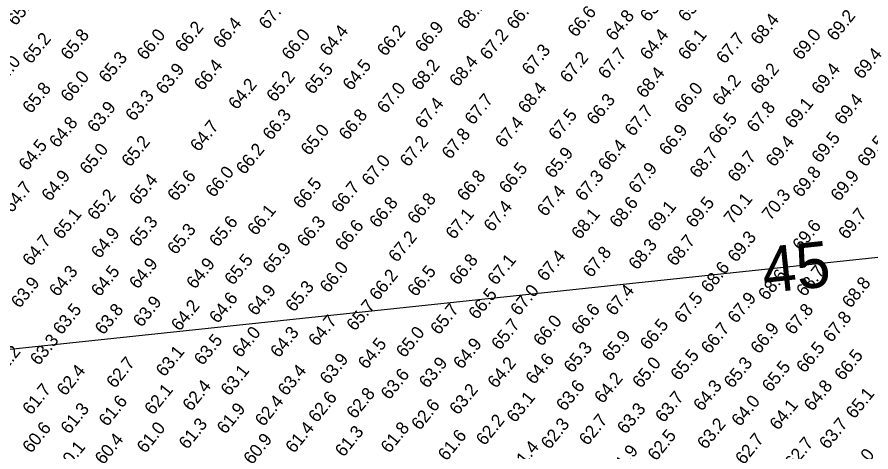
# Model space of a CAD drawing. Extents: x 401290 to 405690, y 1190598 to 1193998.
# Drawn here: x 402509 to 403181, y 1192273 to 1192614 of the extents above; entities that cross this region are included whole.
import ezdxf

# ---------------------------------------------------------------- set-up
doc = ezdxf.new("R2010")
doc.units = 0
for name, color, linetype in [('C-CHAN-CNTR', 7, 'Continuous'), ('V-CHAN-TEXT', 7, 'Continuous'), ('V-TOPO-SOUN', 7, 'Continuous')]:
    doc.layers.add(name, color=color, linetype=linetype)

msp = doc.modelspace()

# ---------------------------------------------------------------- linework, layer by layer
at = {"layer": 'C-CHAN-CNTR'}
msp.add_line((401937.03, 1192293.37), (404340.86, 1192548.17), dxfattribs=at)

# ---------------------------------------------------------------- texts
at = {"layer": 'V-CHAN-TEXT'}
msp.add_text('45', height=36, rotation=6.05064, dxfattribs=at).set_placement((403097.37, 1192397.42))
at = {"layer": 'V-TOPO-SOUN'}
for s, p in [('65.1 ', (402508.18, 1192607.01)), ('67.0 ', (402706.18, 1192604.02)), ('66.8 ', (402901.19, 1192604.02)), ('63.1 ', (403006.18, 1192610.02)), ('65.4 ', (403036.2, 1192610.02)), ('68.1 ', (402862.18, 1192604.02)), ('66.6 ', (402949.19, 1192598.02)), ('64.8 ', (402979.18, 1192595.03)), ('68.4 ', (403093.19, 1192592.01)), ('69.2 ', (403153.19, 1192595.03)), ('66.2 ', (402640.2, 1192586.01)), ('66.4 ', (402670.19, 1192589.03)), ('66.9 ', (402829.18, 1192586.01)), ('65.2 ', (402520.19, 1192577.02)), ('65.8 ', (402550.18, 1192580)), ('66.0 ', (402610.18, 1192580)), ('66.0 ', (402724.19, 1192580)), ('64.4 ', (402754.18, 1192583.02)), ('66.2 ', (402799.19, 1192583.02)), ('67.2 ', (402880.19, 1192580)), ('64.4 ', (403006.18, 1192580)), ('66.1 ', (403036.2, 1192580)), ('67.7 ', (403066.19, 1192577.02)), ('69.0 ', (403126.19, 1192580)), ('67.3 ', (402913.2, 1192568.03)), ('67.7 ', (402973.17, 1192565.01)), ('69.4 ', (403174.19, 1192565.01)), ('64.0 ', (402496.17, 1192559.01)), ('65.3 ', (402580.2, 1192562.03)), ('64.5 ', (402772.19, 1192556.02)), ('68.4 ', (402856.18, 1192559.01)), ('67.2 ', (402943.19, 1192562.03)), ('63.9 ', (402625.18, 1192553.04)), ('66.4 ', (402655.2, 1192556.02)), ('65.5 ', (402742.17, 1192553.04)), ('68.2 ', (402826.19, 1192556.02)), ('68.4 ', (403003.19, 1192550.02)), ('68.2 ', (403093.19, 1192553.04)), ('69.4 ', (403141.19, 1192553.04)), ('66.0 ', (402550.18, 1192547.03)), ('65.2 ', (402712.18, 1192547.03)), ('64.2 ', (403063.2, 1192544.01)), ('65.8 ', (402520.19, 1192538.01)), ('64.2 ', (402682.2, 1192541.03)), ('67.0 ', (402799.19, 1192538.01)), ('68.4 ', (402910.18, 1192538.01)), ('66.0 ', (403033.18, 1192538.01)), ('63.3 ', (402601.19, 1192532.01)), ('67.7 ', (402868.19, 1192529.02)), ('67.4 ', (402829.18, 1192526.04)), ('66.3 ', (402964.18, 1192529.02)), ('67.8 ', (403090.2, 1192523.02)), ('69.1 ', (403120.19, 1192526.04)), ('69.4 ', (403159.2, 1192529.02)), ('63.9 ', (402571.17, 1192523.02)), ('66.3 ', (402709.2, 1192517.01)), ('66.8 ', (402769.17, 1192517.01)), ('67.5 ', (402934.2, 1192517.01)), ('67.7 ', (402994.17, 1192520.03)), ('64.8 ', (402541.19, 1192511.01)), ('67.4 ', (402892.2, 1192511.01)), ('66.5 ', (403060.18, 1192514.03)), ('64.7 ', (402652.18, 1192508.02)), ('65.0 ', (402739.18, 1192505.01)), ('66.9 ', (403021.17, 1192505.01)), ('65.2 ', (402598.17, 1192496.02)), ('67.2 ', (402817.2, 1192496.02)), ('67.8 ', (402850.18, 1192502.02)), ('69.4 ', (403105.19, 1192496.02)), ('69.5 ', (403141.19, 1192499.03)), ('69.5 ', (403177.18, 1192496.02)), ('64.5 ', (402517.17, 1192493.03)), ('65.0 ', (402565.2, 1192490.01)), ('66.2 ', (402688.2, 1192490.01)), ('66.4 ', (402973.17, 1192493.03)), ('65.9 ', (402931.18, 1192487.03)), ('68.7 ', (403045.19, 1192487.03)), ('69.7 ', (403075.17, 1192484.01)), ('67.0 ', (402787.18, 1192481.02)), ('65.6 ', (402634.2, 1192469.01)), ('66.0 ', (402664.18, 1192472.03)), ('66.5 ', (402895.19, 1192475.02)), ('67.9 ', (402997.19, 1192475.02)), ('69.8 ', (403126.19, 1192472.03)), ('64.9 ', (402535.18, 1192469.01)), ('65.4 ', (402604.18, 1192466.03)), ('66.5 ', (402733.18, 1192463.01)), ('66.8 ', (402862.18, 1192469.01)), ('67.3 ', (402955.19, 1192469.01)), ('69.9 ', (403156.18, 1192469.01)), ('64.7 ', (402505.2, 1192460.02)), ('66.7 ', (402763.2, 1192460.02)), ('67.4 ', (402925.18, 1192457.01)), ('65.2 ', (402571.17, 1192454.02)), ('66.8 ', (402823.17, 1192451.04)), ('70.1 ', (403072.19, 1192451.04)), ('70.3 ', (403102.18, 1192454.02)), ('66.8 ', (402793.19, 1192448.02)), ('67.4 ', (402883.18, 1192445.03)), ('68.6 ', (402982.2, 1192448.02)), ('69.1 ', (403012.18, 1192445.03)), ('69.5 ', (403042.2, 1192448.02)), ('65.1 ', (402544.17, 1192439.03)), ('66.1 ', (402697.19, 1192442.01)), ('67.1 ', (402853.19, 1192439.03)), ('68.1 ', (402952.18, 1192439.03)), ('69.7 ', (403162.18, 1192439.03)), ('65.3 ', (402604.18, 1192433.02)), ('65.6 ', (402667.17, 1192433.02)), ('66.3 ', (402736.2, 1192433.02)), ('66.6 ', (402766.19, 1192430.01)), ('69.6 ', (403126.19, 1192430.01)), ('64.9 ', (402574.19, 1192424.03)), ('65.3 ', (402634.2, 1192427.02)), ('64.7 ', (402520.19, 1192418.03)), ('67.2 ', (402808.18, 1192421.02)), ('68.7 ', (403027.18, 1192418.03)), ('69.3 ', (403075.17, 1192421.02)), ('65.9 ', (402709.2, 1192412.03)), ('67.8 ', (402961.2, 1192409.01)), ('68.3 ', (402997.19, 1192415.01)), ('65.5 ', (402679.18, 1192403.04)), ('66.8 ', (402856.18, 1192403.04)), ('67.1 ', (402886.2, 1192403.04)), ('67.4 ', (402925.18, 1192406.02)), ('64.9 ', (402604.18, 1192400.02)), ('64.9 ', (402649.19, 1192400.02)), ('66.0 ', (402754.18, 1192397.03)), ('68.6 ', (403054.18, 1192397.03)), ('64.3 ', (402541.19, 1192394.01)), ('64.5 ', (402574.19, 1192394.01)), ('66.2 ', (402793.19, 1192391.03)), ('66.5 ', (402823.17, 1192394.01)), ('68.6 ', (403099.19, 1192391.03)), ('68.7 ', (403129.18, 1192394.01)), ('63.9 ', (402511.2, 1192385.03)), ('65.3 ', (402727.18, 1192382.01)), ('68.8 ', (403165.2, 1192385.03)), ('64.9 ', (402697.19, 1192379.02)), ('66.5 ', (402871.17, 1192376.04)), ('67.0 ', (402904.18, 1192379.02)), ('67.4 ', (402979.18, 1192379.02)), ('63.9 ', (402607.2, 1192370.03)), ('64.6 ', (402667.17, 1192373.02)), ('67.5 ', (403033.18, 1192373.02)), ('67.9 ', (403075.17, 1192373.02)), ('63.5 ', (402544.17, 1192364.03)), ('63.8 ', (402577.18, 1192364.03)), ('64.2 ', (402637.18, 1192367.01)), ('65.7 ', (402775.18, 1192367.01)), ('65.7 ', (402841.19, 1192364.03)), ('66.6 ', (402952.18, 1192364.03)), ('67.8 ', (403120.19, 1192364.03)), ('64.7 ', (402745.19, 1192355.01)), ('66.0 ', (402922.19, 1192355.01)), ('67.8 ', (403150.17, 1192358.02)), ('65.7 ', (402889.18, 1192352.02)), ('66.5 ', (403006.18, 1192352.02)), ('66.7 ', (403054.18, 1192349.03)), ('66.9 ', (403093.19, 1192349.03)), ('64.0 ', (402685.18, 1192346.02)), ('64.3 ', (402715.2, 1192346.02)), ('65.0 ', (402814.18, 1192346.02)), ('65.9 ', (402976.19, 1192343.03)), ('63.3 ', (402526.19, 1192340.01)), ('63.5 ', (402655.2, 1192340.01)), ('64.5 ', (402784.2, 1192337.03)), ('64.9 ', (402859.2, 1192337.03)), ('62.2 ', (402496.17, 1192331.02)), ('63.1 ', (402625.18, 1192331.02)), ('65.3 ', (402946.17, 1192334.01)), ('65.5 ', (403030.19, 1192328.04)), ('66.5 ', (403129.18, 1192334.01)), ('66.5 ', (403159.2, 1192328.04)), ('62.7 ', (402586.2, 1192322.03)), ('63.9 ', (402754.18, 1192325.02)), ('63.9 ', (402832.2, 1192322.03)), ('64.2 ', (402886.2, 1192322.03)), ('64.6 ', (402916.19, 1192325.02)), ('65.0 ', (403000.18, 1192322.03)), ('65.3 ', (403072.19, 1192322.03)), ('62.4 ', (402547.19, 1192316.03)), ('63.1 ', (402676.19, 1192316.03)), ('63.4 ', (402721.17, 1192316.03)), ('65.5 ', (403102.18, 1192319.01)), ('63.6 ', (402802.18, 1192313.01)), ('64.2 ', (402970.19, 1192310.03)), ('61.7 ', (402520.19, 1192301.04)), ('62.4 ', (402646.17, 1192304.02)), ('63.6 ', (402940.2, 1192304.02)), ('64.3 ', (403048.17, 1192304.02)), ('64.8 ', (403135.18, 1192304.02)), ('62.1 ', (402616.19, 1192301.04)), ('62.6 ', (402745.19, 1192295.03)), ('62.8 ', (402775.18, 1192298.02)), ('63.2 ', (402856.18, 1192301.04)), ('63.7 ', (403018.19, 1192295.03)), ('65.1 ', (403168.19, 1192298.02)), ('61.6 ', (402580.2, 1192292.01)), ('62.4 ', (402703.19, 1192292.01)), ('62.6 ', (402826.19, 1192289.03)), ('63.1 ', (402901.19, 1192295.03)), ('64.0 ', (403078.19, 1192292.01)), ('64.1 ', (403108.18, 1192289.03)), ('61.3 ', (402550.18, 1192286.01)), ('61.9 ', (402673.17, 1192286.01)), ('63.3 ', (402988.2, 1192286.01)), ('62.2 ', (402877.18, 1192277.02)), ('62.7 ', (402958.18, 1192277.02)), ('63.7 ', (403147.19, 1192274.03)), ('60.6 ', (402520.19, 1192271.02)), ('61.0 ', (402610.18, 1192271.02)), ('61.3 ', (402643.19, 1192274.03)), ('61.4 ', (402727.18, 1192271.02)), ('61.3 ', (402766.19, 1192268.03)), ('61.8 ', (402802.18, 1192271.02)), ('62.3 ', (402928.19, 1192274.03)), ('63.2 ', (403051.19, 1192274.03)), ('60.4 ', (402577.18, 1192262.03)), ('60.9 ', (402694.17, 1192262.03)), ('61.6 ', (402847.19, 1192265.01)), ('62.5 ', (403012.18, 1192265.01)), ('62.7 ', (403081.18, 1192262.03)), ('60.1 ', (402547.19, 1192256.02)), ('61.4 ', (402904.18, 1192256.02)), ('62.7 ', (403120.19, 1192259.01)), ('61.9 ', (402982.2, 1192253.04)), ('63.0 ', (403168.19, 1192250.02))]:
    msp.add_text(s, height=9.996, rotation=51.05, dxfattribs=at).set_placement(p)

doc.saveas('drawing.dxf')
